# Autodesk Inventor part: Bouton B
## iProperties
Created: 2010-07
Part Number: Bouton B
Document SubType Name: Modeling
Designer: eric
Density: 1 g/cm^3
Mass: 0.619043 g
Surface Area: 13.6716 cm^2
Volume: 0.619043 cm^3
Author: eric
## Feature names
1. Extrusion2
2. Extrusion1
3. Base1
